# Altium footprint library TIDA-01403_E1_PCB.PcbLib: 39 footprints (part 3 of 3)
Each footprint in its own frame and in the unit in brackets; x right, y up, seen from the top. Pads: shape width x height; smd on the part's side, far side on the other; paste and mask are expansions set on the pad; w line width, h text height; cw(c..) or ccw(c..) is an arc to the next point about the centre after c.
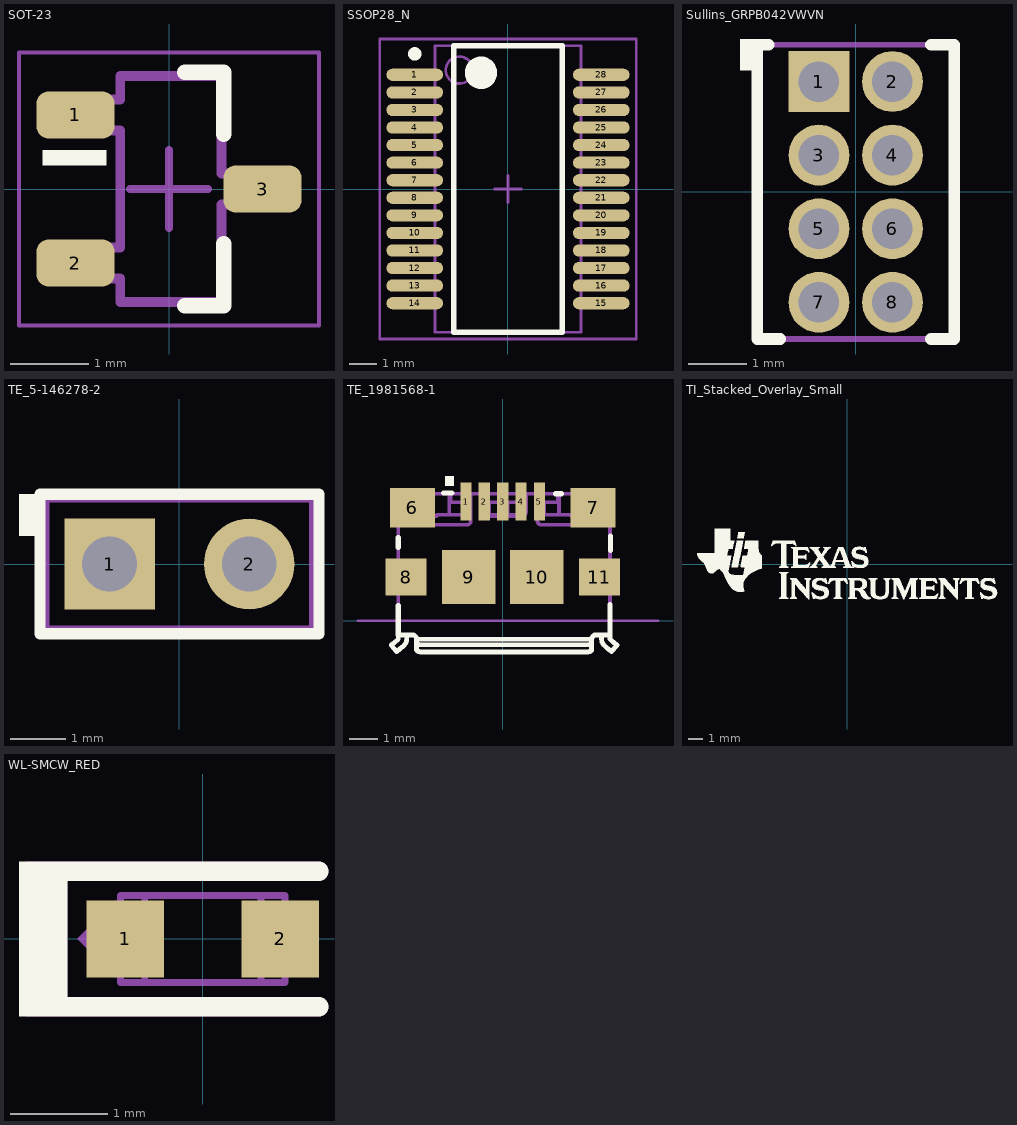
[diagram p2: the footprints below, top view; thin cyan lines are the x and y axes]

## SOT-23 [mm] "SOT23, 3-Leads, Body 2.9x1.3mm, Pitch 0.95mm, Lead Span 2.5mm, IPC Medium Density"
height 1.1
pads (3):
  rrect50% 1x0.6 smd: 1(-1.2,0.95) 2(-1.2,-0.95) 3(1.2,0)
Top Overlay:
  rectangle: -1.625,0.3 -0.8,0.5
  lines w0.2: 0.2,-1.5 0.7,-1.5 0.7,-0.7 ; 0.2,1.5 0.7,1.5 0.7,0.7
Mechanical 5:
  lines w0.127: -1.16,-1.15 -0.625,-1.15 -0.625,-1.45 0.675,-1.45 0.675,-0.2 1.21,-0.2 1.21,0.2 0.675,0.2 0.675,1.45 -0.625,1.45 -0.625,1.15 -1.16,1.15 -1.16,0.75 -0.625,0.75 -0.625,-0.75 -1.16,-0.75 -1.16,-1.15
  text ".Designator" at -0.175,1.225 h0.76
Mechanical 15:
  lines w0.05: -1.925,-1.75 -1.925,1.75 1.925,1.75 1.925,-1.75 -1.925,-1.75
  lines w0.1: -0.5,0 0.5,0 ; 0,-0.5 0,0.5
3D body "SW3dPS-sot-3p290x130ll237h100.STEP": height 1, standoff 0, extent -1.16,-1.45 1.21,1.45

## SSOP28_N [mm] "SOP, 28-Leads, Body 10.2x5.3mm, Pitch 0.65mm, IPC Medium Density"
height 2
pads (28):
  oval 2.1x0.45 smd: 1(-3.45,4.225) 2(-3.45,3.575) 3(-3.45,2.925) 4(-3.45,2.275) 5(-3.45,1.625) 6(-3.45,0.975) 7(-3.45,0.325) 8(-3.45,-0.325) 9(-3.45,-0.975) 10(-3.45,-1.625) 11(-3.45,-2.275) 12(-3.45,-2.925) 13(-3.45,-3.575) 14(-3.45,-4.225) 15(3.45,-4.225) 16(3.45,-3.575) 17(3.45,-2.925) 18(3.45,-2.275) 19(3.45,-1.625) 20(3.45,-0.975) 21(3.45,-0.325) 22(3.45,0.325) 23(3.45,0.975) 24(3.45,1.625) 25(3.45,2.275) 26(3.45,2.925) 27(3.45,3.575) 28(3.45,4.225)
Top Overlay:
  circle w0.25: c-3.45,5 r0.125
  circle w0.6: c-1,4.3 r0.3
  lines w0.2: -2,-5.3 -2,5.3 2,5.3 2,-5.3 -2,-5.3
Mechanical 5:
  circle w0.1: c-1.8,4.4 r0.5
  lines w0.1: -2.7,-5.3 -2.7,5.3 2.7,5.3 2.7,-5.3 -2.7,-5.3
  text ".Designator" at -1.524,-0.508 h0.76
Mechanical 15:
  lines w0.1: -0.5,0 0.5,0 ; 0,-0.5 0,0.5 ; -4.75,-5.55 -4.75,5.55 4.75,5.55 4.75,-5.55 -4.75,-5.55
3D body: height 2, standoff 0, extent -2.7,-5.3 2.7,5.3

## Sullins_GRPB042VWVN [mm] "Header, 1.27mm, 4x2, TH"
height 4
pads (8):
  rect 1.05x1.05 hole 0.7: 1(-0.635,1.905)
  round 1.05 hole 0.7: 2(0.635,1.905) 3(-0.635,0.635) 4(0.635,0.635) 5(-0.635,-0.635) 6(0.635,-0.635) 7(-0.635,-1.905) 8(0.635,-1.905)
Top Overlay:
  rectangle: -2,2.1 -1.7,2.64
  lines w0.2: -1.5,2.54 -1.7,2.54 -1.7,-2.54 -1.3,-2.54 ; 1.3,-2.54 1.7,-2.54 1.7,2.54 1.3,2.54
Mechanical 5:
  lines w0.1: -1.7,-2.54 -1.7,2.54 1.7,2.54 1.7,-2.54 -1.7,-2.54
  text ".Designator" at -0.508,1.524 h0.76
3D body: height 4, standoff -2.3, extent -0.835,-2.105 -0.435,-1.705
3D body: height 4, standoff -2.3, extent 0.435,-2.105 0.835,-1.705
3D body: height 4, standoff -2.3, extent 0.435,-0.835 0.835,-0.435
3D body: height 4, standoff -2.3, extent -0.835,-0.835 -0.435,-0.435
3D body: height 4, standoff -2.3, extent -0.835,0.435 -0.435,0.835
3D body: height 4, standoff -2.3, extent 0.435,0.435 0.835,0.835
3D body: height 4, standoff -2.3, extent 0.435,1.705 0.835,2.105
3D body: height 4, standoff -2.3, extent -0.835,1.705 -0.435,2.105
3D body: height 1, standoff 0, extent -1.699,-2.539 1.699,2.539

## TE_5-146278-2 [mm] "TE CONNECTIVITY"
height 8.128
pads (2):
  rect 1.65x1.65 hole 1: 1(-1.27,0)
  round 1.65 hole 1: 2(1.27,0)
Top Overlay:
  rectangle: -2.921,0.508 -2.54,1.27
  lines w0.203: -2.54,-1.27 -2.54,1.27 2.54,1.27 2.54,-1.27 -2.54,-1.27
Mechanical 5:
  lines w0.102: -2.413,-1.168 -2.413,1.168 2.413,1.168 2.413,-1.168 -2.413,-1.168
  text ".Designator" at -2.032,-0.381 h0.76
3D body: height 8.13, standoff -3.05, extent -1.587,-0.317 -0.952,0.318
3D body: height 8.13, standoff -3.05, extent 0.953,-0.317 1.588,0.318
3D body: height 2.29, standoff 0, extent -2.412,-1.168 2.412,1.168

## TE_1981568-1 [mm] "TE Connectivity"
height 3.2
pads (11):
  rect 0.4x1.35 smd: 1(-1.3,4.225) 2(-0.65,4.225) 3(0,4.225) 4(0.65,4.225) 5(1.3,4.225)
  rect 1.6x1.4 smd: 6(-3.2,4) 7(3.2,4)
  rect 1.45x1.3 smd: 8(-3.425,1.55) 11(3.425,1.55)
  rect 1.9x1.9 smd: 9(-1.2,1.55) 10(1.2,1.55)
Top Overlay:
  drawing of 158 lines, arcs and shapes, not listed
Mechanical 1:
  lines w0.1: -5.125,0 5.5,0
  text "Board Edge" at -6.35,-0.975 h0.7
Mechanical 5:
  drawing of 230 lines, arcs and shapes, not listed
  text ".Designator" at -1.75,1.225 h0.76
3D body "TE_1981568-1.stp": height 2.79, standoff -0.29, extent -3.975,-1.125 4.025,4.475

## TI_Stacked_Overlay_Small [mm]
Top Overlay:
  drawing of 18 lines, arcs and shapes, not listed

## WL-SMCW_RED [mm] "WURTH"
height 0.8
pads (2):
  rect 0.8x0.8 smd: 1(-0.8,0) 2(0.8,0)
Top Overlay:
  rectangle: -1.9,-0.8 -1.4,0.8
  lines w0.2: -1.6,-0.7 1.2,-0.7 ; -1.6,0.7 1.2,0.7
Mechanical 5:
  region: -0.9,-0.4 -0.9,0.4 -1.3,0
  lines w0.2: -1.65,-0.7 -1.65,0.55 ; 1.2,-0.7 -1.5,-0.7 ; 1.2,0.7 -1.5,0.7 ; -1.5,-0.7 -1.8,-0.7 -1.8,0.7 -1.5,0.7 ; -1.5,-0.7 -1.5,0.7
  text ".Designator" at -0.8,-0.3 h0.76
Mechanical 13:
  lines w0.07: -0.6,-0.45 -0.6,0.45 ; 0.6,-0.45 0.6,0.45 ; -0.85,-0.45 0.85,-0.45 0.85,0.45 -0.85,0.45 -0.85,-0.45
3D body: height 0.8, standoff 0.35, extent -0.599,-0.449 0.599,0.449
3D body: height 0.35, standoff 0, extent 0.601,-0.449 0.849,0.449
3D body: height 0.35, standoff 0, extent -0.599,-0.449 0.599,0.449
3D body: height 0.35, standoff 0, extent -0.849,-0.449 -0.601,0.449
